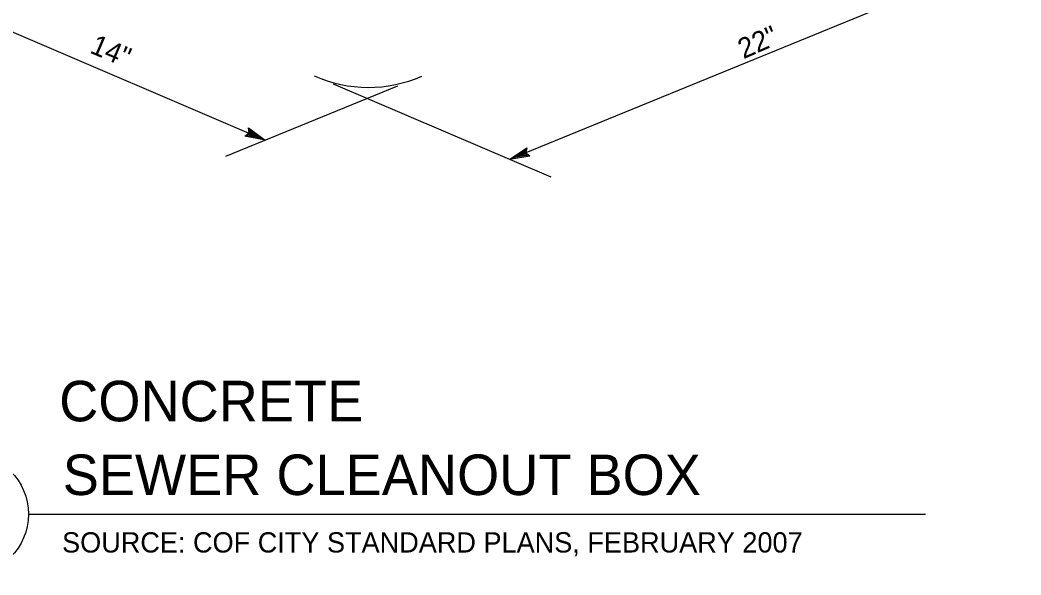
# Model space of a CAD drawing. Extents: x -123486 to -116575, y -107066 to -101122.
# Drawn here: x -117192.1 to -116895.6, y -101654.1 to -101489.7 of the extents above; entities that cross this region are included whole.
import ezdxf

# ---------------------------------------------------------------- set-up
doc = ezdxf.new("R2010")
doc.units = 0
for name, color, linetype in [('G-MARK', 7, 'Continuous'), ('G-TEXT', 7, 'Continuous'), ('Misc CnstDet(22)', 7, 'Continuous')]:
    doc.layers.add(name, color=color, linetype=linetype)

msp = doc.modelspace()

# ---------------------------------------------------------------- linework, layer by layer
at = {"layer": 'G-MARK'}
for p, q in [((-116895.6, -101469.09), (-117047.1, -101531.02)), ((-117225.38, -101480.05), (-117119.46, -101525.32)), ((-117080.3, -101509.32), (-117131.19, -101530.12)), ((-117034.75, -101536.3), (-117099.22, -101508.74))]:
    msp.add_line(p, q, dxfattribs=at)
at = {"layer": 'G-TEXT'}
for p, q in [((-117124.22, -101523.24), (-117124.42, -101521.7)), ((-117124.42, -101521.7), (-117124.42, -101521.7)), ((-117124.42, -101521.7), (-117119.46, -101525.32)), ((-117125.49, -101524.14), (-117124.22, -101523.24)), ((-117119.46, -101525.32), (-117125.49, -101524.14)), ((-117125.49, -101524.14), (-117125.49, -101524.14)), ((-117120.73, -101524.77), (-117125.13, -101523.91)), ((-117121.99, -101524.22), (-117124.83, -101523.66)), ((-117123.26, -101523.66), (-117124.47, -101523.43)), ((-117124.37, -101522.11), (-117120.72, -101524.77)), ((-117124.3, -101522.53), (-117121.99, -101524.22)), ((-117124.27, -101522.92), (-117123.26, -101523.66)), ((-117119.46, -101525.32), (-117119.46, -101525.32)), ((-117047.1, -101531.02), (-117042.01, -101527.58)), ((-117042.01, -101527.58), (-117042.27, -101529.11)), ((-117042.01, -101527.58), (-117042.01, -101527.58)), ((-117041.03, -101530.06), (-117047.1, -101531.02)), ((-117041.36, -101529.81), (-117045.82, -101530.51)), ((-117045.81, -101530.51), (-117042.1, -101528)), ((-117044.53, -101530.01), (-117042.14, -101528.39)), ((-117041.71, -101529.56), (-117044.53, -101530.01)), ((-117043.25, -101529.5), (-117042.22, -101528.81)), ((-117042, -101529.3), (-117043.25, -101529.5)), ((-117042.27, -101529.11), (-117041.03, -101530.06)), ((-117041.03, -101530.06), (-117041.03, -101530.06)), ((-117047.1, -101531.02), (-117047.1, -101531.02))]:
    msp.add_line(p, q, dxfattribs=at)
at = {"layer": 'Misc CnstDet(22)'}
msp.add_line((-117189.59, -101636.1), (-116923.84, -101636.1), dxfattribs=at)
msp.add_circle((-117207.59, -101636.1), 18, dxfattribs=at)
msp.add_arc((-117088.93, -101470.3), 39.39, 246.0493, 293.7493, dxfattribs=at)

# ---------------------------------------------------------------- texts
for s, rotation, p in [('22"', 23.6156, (-116977.79, -101501.37)), ('14"', 337.0306, (-117171.69, -101499.34))]:
    msp.add_text(s, height=6, rotation=rotation, dxfattribs=at).set_placement(p)
for s, height, p in [('CONCRETE', 12, (-117180.47, -101608.6)), ('SEWER CLEANOUT BOX', 12, (-117179.43, -101630.43)), ('SOURCE: COF CITY STANDARD PLANS, FEBRUARY 2007', 6, (-117179.62, -101647.45))]:
    msp.add_text(s, height=height, dxfattribs=at).set_placement(p)

doc.saveas('drawing.dxf')
